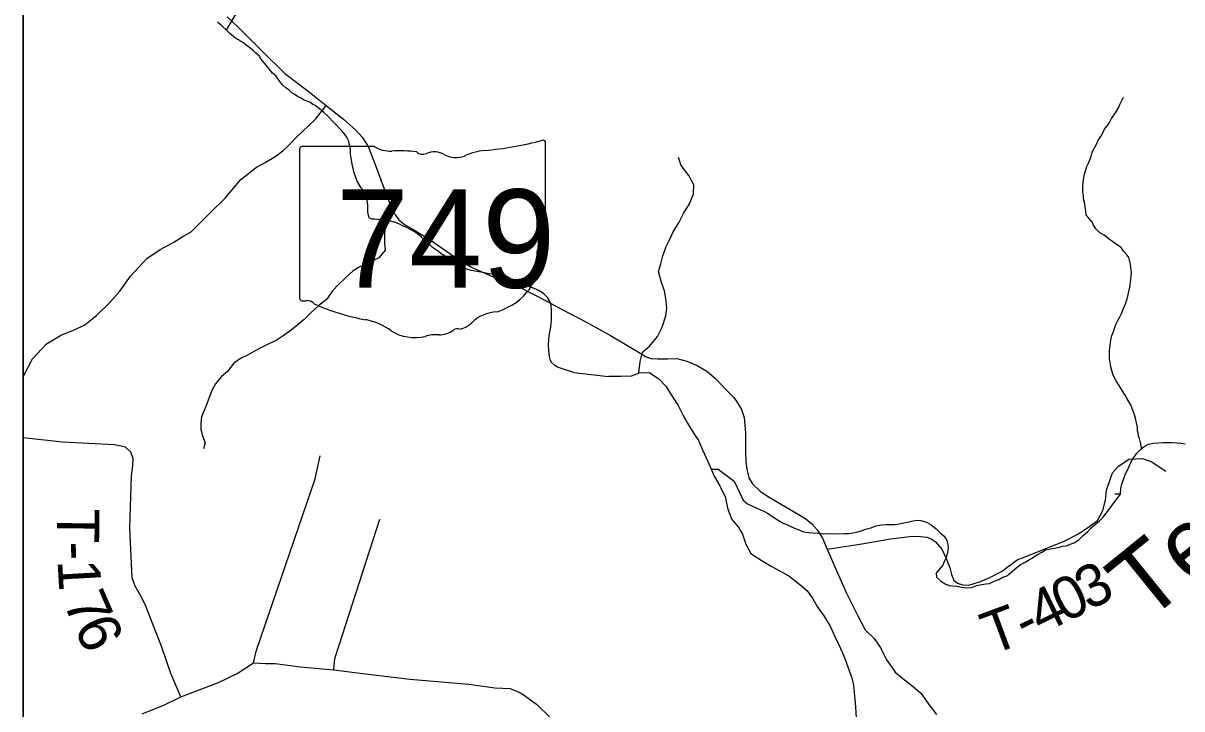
# Model space of a CAD drawing. Extents: x 0 to 39.3, y -3.9 to 22.
# Drawn here: x 1.9 to 3.453, y 16.173 to 17.092 of the extents above; entities that cross this region are included whole.
import ezdxf

# ---------------------------------------------------------------- set-up
doc = ezdxf.new("R2010")
doc.units = 0
for name, color, linetype in [('GM_X_Corporation', 7, 'Continuous'), ('GM_X_Minor_River', 7, 'Continuous'), ('GM_X_Minor_River_Text', 7, 'Continuous'), ('GM_X_State_Location', 7, 'Continuous'), ('GM_X_State_Route', 7, 'Continuous'), ('GM_X_State_Shield', 7, 'Continuous'), ('GM_X_Township_Road', 7, 'Continuous'), ('GM_X_Township_Road_Text', 7, 'Continuous'), ('SH_Data', 7, 'Continuous')]:
    doc.layers.add(name, color=color, linetype=linetype)

msp = doc.modelspace()

# ---------------------------------------------------------------- linework, layer by layer
at = {"layer": 'GM_X_Corporation'}
msp.add_lwpolyline([(1.9, 20.2403), (1.9, 15.8496), (1.9627, 15.8365), (2.054, 15.8197), (2.1447, 15.8042), (2.2384, 15.7885), (2.3314, 15.7727), (2.3534, 15.7684), (2.406, 15.7581), (2.4514, 15.75), (2.5183, 15.7585), (2.5893, 15.7591), (2.6537, 15.7535), (2.8288, 15.7458), (2.8431, 15.7483), (3.5402, 15.8703)], dxfattribs=at)
at = {"layer": 'GM_X_Minor_River'}
for points in [[(2.1724, 17.0821), (2.1899, 17.1123)], [(2.2519, 17.0051), (2.2478, 17.0086), (2.2441, 17.0136), (2.2385, 17.0213), (2.234, 17.0248), (2.2292, 17.031), (2.2251, 17.036), (2.221, 17.0406), (2.218, 17.0445), (2.2169, 17.0476), (2.2116, 17.0515), (2.2087, 17.0545), (2.2034, 17.0592), (2.1985, 17.0627), (2.1952, 17.0654), (2.1914, 17.0674), (2.1884, 17.0694), (2.185, 17.0713), (2.182, 17.0737), (2.1767, 17.0783), (2.1719, 17.0826), (2.1666, 17.0876), (2.1606, 17.093)], [(2.6379, 16.6236), (2.6341, 16.6248), (2.6265, 16.6269), (2.6227, 16.6281), (2.6159, 16.6305), (2.6125, 16.6328), (2.6084, 16.6363), (2.6069, 16.6394), (2.6055, 16.6447), (2.6045, 16.6531), (2.6039, 16.6611), (2.6044, 16.6683), (2.6053, 16.6752), (2.6065, 16.6816), (2.6074, 16.6881), (2.6079, 16.6945), (2.6081, 16.7071), (2.6074, 16.7132), (2.606, 16.7185), (2.6027, 16.7239), (2.5978, 16.7289), (2.5918, 16.7329), (2.5846, 16.736), (2.5778, 16.7388), (2.5631, 16.744), (2.5555, 16.7476), (2.548, 16.7523), (2.5366, 16.7544), (2.5302, 16.7552), (2.5245, 16.7557), (2.52, 16.7566), (2.5135, 16.7578), (2.5002, 16.7603), (2.4946, 16.7619), (2.4904, 16.7635), (2.4833, 16.7671), (2.4795, 16.7694), (2.475, 16.7741), (2.4686, 16.7769), (2.4645, 16.78), (2.4603, 16.7827), (2.4566, 16.7854), (2.4524, 16.7882), (2.4487, 16.7909), (2.4453, 16.794), (2.4416, 16.7971), (2.4378, 16.801), (2.4337, 16.8049), (2.4303, 16.808), (2.427, 16.8103), (2.4239, 16.8123), (2.4206, 16.8142), (2.4164, 16.8166), (2.4123, 16.8185), (2.4085, 16.8201), (2.4051, 16.8217), (2.4002, 16.8241), (2.3953, 16.8253), (2.3919, 16.8261), (2.3873, 16.8266), (2.3843, 16.827), (2.3805, 16.8279), (2.3756, 16.8283), (2.371, 16.8288), (2.3676, 16.8288), (2.3638, 16.8308), (2.3617, 16.8385), (2.3618, 16.8487), (2.3601, 16.8583), (2.3594, 16.8617), (2.3576, 16.8659), (2.3546, 16.8686), (2.352, 16.8721), (2.3475, 16.8798), (2.3457, 16.8848), (2.3435, 16.8909), (2.3421, 16.897), (2.3407, 16.9027), (2.34, 16.9085), (2.3393, 16.913), (2.3386, 16.9172), (2.3387, 16.9214), (2.3384, 16.9245), (2.337, 16.9313), (2.3359, 16.9344), (2.3341, 16.9378), (2.3315, 16.9421), (2.3274, 16.9471), (2.3072, 16.968), (2.3027, 16.9723), (2.299, 16.9757), (2.2914, 16.9812), (2.288, 16.9828), (2.2843, 16.9859), (2.2767, 16.9887), (2.2718, 16.9914), (2.2677, 16.9934), (2.2632, 16.9965), (2.2602, 16.9985), (2.2568, 17.0016), (2.2519, 17.0051)], [(3.3993, 16.5219), (3.3981, 16.524), (3.3974, 16.5297), (3.396, 16.535), (3.3949, 16.5381), (3.3942, 16.5419), (3.3935, 16.545), (3.3932, 16.5499), (3.3921, 16.5557), (3.3907, 16.5621), (3.3889, 16.5679), (3.3867, 16.574), (3.3842, 16.5801), (3.3816, 16.5844), (3.3786, 16.5894), (3.3772, 16.5924), (3.3749, 16.5955), (3.3716, 16.6013), (3.3679, 16.6071), (3.3646, 16.6124), (3.362, 16.6171), (3.3602, 16.6213), (3.3591, 16.6259), (3.3577, 16.6308), (3.3566, 16.6362), (3.3559, 16.6415), (3.3557, 16.6484), (3.3557, 16.6529), (3.3566, 16.6598), (3.3571, 16.6639), (3.3579, 16.6689), (3.3591, 16.673), (3.3607, 16.6772), (3.3619, 16.681), (3.3643, 16.6878), (3.3667, 16.6923), (3.3694, 16.6972), (3.371, 16.7006), (3.3722, 16.7036), (3.3742, 16.7081), (3.3773, 16.7153), (3.3797, 16.7221), (3.3814, 16.7297), (3.383, 16.7377), (3.3843, 16.7475), (3.3853, 16.7574), (3.3849, 16.7608), (3.3839, 16.7688), (3.3825, 16.7738), (3.3818, 16.7776), (3.3796, 16.7807), (3.3751, 16.7857), (3.3714, 16.7911), (3.365, 16.795), (3.3597, 16.7989), (3.356, 16.8017), (3.3485, 16.8075), (3.3428, 16.8106), (3.3376, 16.8161), (3.3342, 16.8207), (3.3332, 16.8245), (3.3283, 16.8303), (3.3246, 16.8342), (3.3243, 16.8399), (3.3233, 16.8452), (3.3229, 16.8494), (3.3212, 16.8563), (3.3208, 16.8601), (3.3202, 16.8654), (3.3203, 16.8727), (3.3207, 16.8772), (3.3212, 16.8822), (3.3225, 16.8894), (3.3241, 16.895), (3.3253, 16.8996), (3.3281, 16.9049), (3.3312, 16.9132), (3.3321, 16.917), (3.3336, 16.9204), (3.3364, 16.9253), (3.3384, 16.9294), (3.3407, 16.9347), (3.345, 16.9411), (3.3493, 16.9494), (3.3544, 16.9561), (3.3564, 16.9595), (3.3583, 16.9641), (3.3607, 16.9671), (3.3649, 16.9727), (3.3677, 16.978), (3.3697, 16.9825), (3.3709, 16.9855), (3.3728, 16.9889), (3.3748, 16.9927)], [(2.725, 16.6228), (2.7269, 16.6383), (2.7298, 16.6505), (2.7394, 16.6587), (2.7499, 16.6718), (2.7562, 16.6842), (2.7614, 16.6993), (2.7627, 16.7103), (2.7614, 16.7225), (2.7593, 16.7328), (2.7553, 16.7439), (2.7514, 16.7588), (2.7546, 16.769), (2.7571, 16.7796), (2.7619, 16.7921), (2.7666, 16.8023), (2.7713, 16.8121), (2.7791, 16.8249), (2.785, 16.8366), (2.7929, 16.8493), (2.7984, 16.8629), (2.7986, 16.8751), (2.792, 16.8874), (2.7816, 16.9009), (2.7783, 16.9116)], [(2.3848, 16.827), (2.3841, 16.7966), (2.3851, 16.7875), (2.3766, 16.7769), (2.3609, 16.7696), (2.3505, 16.7645), (2.3421, 16.7597), (2.332, 16.7503), (2.3228, 16.7414), (2.3146, 16.7328), (2.3068, 16.7219), (2.2964, 16.7133), (2.2856, 16.7032), (2.2767, 16.6946), (2.2659, 16.6857), (2.2575, 16.679), (2.2486, 16.6727), (2.239, 16.6664), (2.2294, 16.662), (2.2187, 16.6565), (2.2102, 16.652), (2.2006, 16.6465), (2.1914, 16.6421), (2.1822, 16.6358), (2.1737, 16.6249), (2.1652, 16.6174), (2.1578, 16.6084), (2.1531, 16.6002), (2.1491, 16.59), (2.1463, 16.5813), (2.1424, 16.5726), (2.1388, 16.5639), (2.1379, 16.5555), (2.1381, 16.5468), (2.1403, 16.5384), (2.1439, 16.5292), (2.1415, 16.5209)], [(2.6379, 16.6236), (2.6844, 16.6182), (2.6852, 16.6186)], [(2.6852, 16.6186), (2.7009, 16.6185), (2.7152, 16.6188), (2.7259, 16.6231), (2.7388, 16.6233), (2.752, 16.6151), (2.7613, 16.6051), (2.7713, 16.5893), (2.778, 16.5793), (2.7846, 16.5659), (2.7905, 16.5555), (2.7986, 16.5417), (2.8049, 16.5321), (2.8108, 16.5187), (2.8152, 16.5091), (2.8196, 16.4991), (2.8262, 16.4846), (2.8336, 16.4715)], [(3.3706, 16.4604), (3.3708, 16.4679), (3.3724, 16.4736), (3.3744, 16.48), (3.3767, 16.4868), (3.3795, 16.4917), (3.3818, 16.4966), (3.3846, 16.5027), (3.3877, 16.5079), (3.3923, 16.5151), (3.3974, 16.5203), (3.4024, 16.5244), (3.4081, 16.5274), (3.415, 16.5288), (3.421, 16.5291), (3.4275, 16.5294), (3.4336, 16.5297), (3.4397, 16.5296), (3.4465, 16.5291), (3.4514, 16.5286), (3.4571, 16.5278)], [(2.8219, 16.4939), (2.8313, 16.494), (2.8529, 16.4778)], [(2.8529, 16.4778), (2.8649, 16.4524), (2.8705, 16.4474), (2.8773, 16.4442), (2.8871, 16.4399), (2.8927, 16.4375), (2.8976, 16.4348), (2.9025, 16.4316), (2.9081, 16.4278), (2.913, 16.4246), (2.9183, 16.4215), (2.9232, 16.4195), (2.9288, 16.4171), (2.9337, 16.4148), (2.9386, 16.4128), (2.9457, 16.41), (2.9525, 16.4088), (2.9578, 16.4083), (2.9662, 16.4078), (2.973, 16.4073), (2.9783, 16.4076), (2.9942, 16.4073), (3.0007, 16.4076), (3.0064, 16.4075), (3.0124, 16.4085), (3.0185, 16.4099), (3.0235, 16.4113), (3.0288, 16.4132), (3.0361, 16.4153), (3.0433, 16.4179), (3.0505, 16.4193), (3.0562, 16.4195), (3.0627, 16.4198), (3.0676, 16.4197), (3.0744, 16.4207), (3.0801, 16.4218), (3.0851, 16.4228), (3.0927, 16.4246), (3.0976, 16.4253), (3.1029, 16.4252), (3.1105, 16.4228), (3.1169, 16.4193), (3.1229, 16.4142), (3.1288, 16.4084), (3.1344, 16.4041), (3.1377, 16.398), (3.1392, 16.393), (3.1395, 16.3873), (3.1382, 16.3801), (3.137, 16.3752), (3.1342, 16.3699), (3.1323, 16.365), (3.1272, 16.359), (3.1234, 16.3542), (3.124, 16.3492), (3.1296, 16.3438), (3.1356, 16.3399), (3.1409, 16.3379), (3.1462, 16.3374), (3.1511, 16.337), (3.1575, 16.3357), (3.164, 16.3349), (3.1712, 16.3351), (3.1781, 16.3377), (3.1849, 16.3394), (3.1902, 16.3401), (3.1952, 16.3404), (3.2013, 16.3437), (3.2074, 16.3459), (3.2131, 16.3492), (3.2181, 16.351), (3.2231, 16.3548), (3.2296, 16.3603), (3.2365, 16.3659), (3.2426, 16.3692), (3.2518, 16.3744), (3.2595, 16.3792), (3.2652, 16.3825), (3.2702, 16.3855), (3.2794, 16.3876), (3.287, 16.389), (3.2927, 16.3904), (3.298, 16.3911), (3.303, 16.3933), (3.3083, 16.3951), (3.3152, 16.3996), (3.3206, 16.4048), (3.3263, 16.4096), (3.3314, 16.4152), (3.3375, 16.4205), (3.3425, 16.4246), (3.3475, 16.4294), (3.3706, 16.4604), (3.3628, 16.4603)], [(2.8336, 16.4715), (2.8351, 16.4686), (2.8406, 16.4567), (2.8445, 16.4403), (2.8496, 16.4265), (2.8581, 16.4165), (2.864, 16.4065), (2.8683, 16.3931), (2.875, 16.3808), (2.8889, 16.3719), (2.9024, 16.3636), (2.9155, 16.3566), (2.9261, 16.3507), (2.9407, 16.3394), (2.9508, 16.3309), (2.9578, 16.3208), (2.9641, 16.3097), (2.973, 16.2974), (2.9815, 16.2835), (2.9877, 16.2697), (2.9928, 16.259), (2.9979, 16.2475), (3.0023, 16.2364), (3.0059, 16.2261), (3.0103, 16.2142), (3.0128, 16.2043), (3.0153, 16.1754), (3.0162, 16.1601)]]:
    msp.add_lwpolyline(points, dxfattribs=at)
at = {"layer": 'GM_X_State_Route'}
msp.add_lwpolyline([(2.1736, 17.1004), (2.1889, 17.0854), (2.22, 17.0544), (2.2505, 17.0244), (2.2814, 17.0011), (2.3061, 16.9812), (2.3293, 16.9629), (2.3456, 16.9481), (2.3541, 16.9389), (2.3624, 16.9264), (2.3718, 16.9023), (2.3836, 16.8696), (2.3926, 16.8464), (2.3987, 16.8346), (2.4035, 16.8281), (2.411, 16.8219), (2.4213, 16.8161), (2.4439, 16.8022), (2.4673, 16.7861), (2.4836, 16.7751), (2.501, 16.7644), (2.5234, 16.7544), (2.5642, 16.7384), (2.6016, 16.7191), (2.6207, 16.7088), (2.6542, 16.6912), (2.6873, 16.6732), (2.7189, 16.6542), (2.7347, 16.6442), (2.7411, 16.6422), (2.7502, 16.6416), (2.7639, 16.6417), (2.7761, 16.6421), (2.7892, 16.6387), (2.8032, 16.6327), (2.816, 16.6251), (2.8278, 16.6154), (2.8426, 16.5998), (2.8522, 16.5897), (2.8575, 16.5827), (2.8625, 16.574), (2.8661, 16.5629), (2.8678, 16.5423), (2.8682, 16.5184), (2.8683, 16.5035), (2.8698, 16.4939), (2.8726, 16.4821), (2.8773, 16.4743), (2.8876, 16.4643), (2.8975, 16.4577), (2.9171, 16.446), (2.9384, 16.4335), (2.9488, 16.4271), (2.9571, 16.4206), (2.964, 16.4123), (2.9712, 16.4012), (2.9776, 16.3867), (2.9891, 16.3596), (3.0033, 16.3277), (3.0185, 16.2971), (3.0283, 16.2785), (3.0403, 16.2666), (3.0483, 16.2554), (3.0574, 16.2378), (3.0686, 16.2216), (3.0787, 16.2132), (3.0932, 16.2022), (3.103, 16.1937), (3.1152, 16.1765), (3.1238, 16.1647)], dxfattribs=at)
at = {"layer": 'GM_X_State_Shield'}
for p, q in [((2.3703, 16.9264), (2.2738, 16.9264)), ((2.6001, 16.8267), (2.6001, 16.9314)), ((2.2705, 16.923), (2.2705, 16.7229)), ((2.6001, 16.8267), (2.6001, 16.8267))]:
    msp.add_line(p, q, dxfattribs=at)
for centre, major_axis, start_param, end_param in [((2.2743, 16.9234), (0.00382, 0), 1.712693, 3.28349), ((2.3933, 16.9497), (0.037, 0), 4.042523, 4.731795), ((2.4827, 17.1993), (0.3495, 0), 4.814394, 5.042369), ((2.5964, 16.9318), (0.00367, 0), 6.141152, 7.989035), ((2.4055, 16.8141), (0.133, 0), 1.404758, 1.657858), ((2.4357, 16.9244), (0.0107, 0), 3.836095, 5.185415), ((2.4514, 16.9013), (0.0222, 0), 0.950623, 2.079405), ((2.4801, 16.933), (0.0267, 0), 4.081561, 5.145723), ((2.5273, 16.8653), (0.0703, 0), 1.699011, 2.107814), ((2.5992, 16.819), (0.00568, 0), 1.883978, 3.671073), ((2.5631, 16.8058), (0.0341, 0), 5.934695, 6.695948), ((2.5962, 16.8263), (0.00393, 0), 5.05454, 6.418171), ((2.6132, 16.7829), (0.0248, 0), 2.387724, 3.262537), ((2.5023, 16.7696), (0.0874, 0), 5.101752, 6.440018), ((2.2743, 16.7224), (0.00385, 0), 3.00124, 4.508301), ((2.2749, 16.7429), (0.0294, 0), 4.665946, 4.897461), ((2.2809, 16.7113), (0.0106, 0), 0.519207, 1.627899), ((2.4147, 16.8911), (0.2524, 0), 4.195997, 4.488961), ((2.3395, 16.633), (0.079, 0), 0.823519, 1.323587), ((2.5391, 16.6667), (0.0479, 0), 1.647645, 2.488434), ((2.4249, 16.7103), (0.0501, 0), 4.026481, 4.996735), ((2.4575, 16.6953), (0.0267, 0), 4.691044, 5.507374), ((2.4817, 16.676), (0.00752, 0), 1.147584, 2.315152), ((2.4785, 16.7035), (0.0282, 0), 4.937069, 5.64225), ((2.4539, 16.6411), (0.0412, 0), 1.495662, 1.94098)]:
    msp.add_ellipse(centre, major_axis=major_axis, ratio=0.8, start_param=start_param, end_param=end_param, dxfattribs=at)
at = {"layer": 'GM_X_Township_Road'}
for points in [[(1.9, 16.6176), (1.9123, 16.6418), (1.9313, 16.6619), (1.9512, 16.6741), (1.9689, 16.6804), (1.9827, 16.6874), (1.9982, 16.6998), (2.0152, 16.7163), (2.0295, 16.7325), (2.0439, 16.7527), (2.0659, 16.7762), (2.0836, 16.7885), (2.1019, 16.798), (2.1141, 16.8058), (2.1256, 16.8126), (2.15, 16.8372), (2.1705, 16.8573), (2.1919, 16.8823), (2.2127, 16.8987), (2.2242, 16.9049), (2.2384, 16.9133), (2.2481, 16.9207), (2.255, 16.9271), (2.2655, 16.9382), (2.2917, 16.9632), (2.3061, 16.9812)], [(2.1114, 16.1885), (2.098, 16.2199), (2.0858, 16.2554), (2.0635, 16.3124), (2.0567, 16.3254), (2.0499, 16.3371), (2.0459, 16.3481), (2.0428, 16.4152), (2.045, 16.4849), (2.0471, 16.4989), (2.0475, 16.5079), (2.0444, 16.5166), (2.037, 16.5233), (2.0224, 16.5264), (1.9528, 16.5302), (1.9, 16.536)], [(2.2088, 16.2342), (2.2129, 16.251), (2.2574, 16.3815), (2.2915, 16.4808), (2.2978, 16.5118)], [(3.2239, 16.3661), (3.2274, 16.3685), (3.2332, 16.3729), (3.2405, 16.3753), (3.2953, 16.3971), (3.3142, 16.4072), (3.3296, 16.4174), (3.3397, 16.4248), (3.3468, 16.4383), (3.3506, 16.4522), (3.3518, 16.4655), (3.3597, 16.4887), (3.3674, 16.4974), (3.3819, 16.507), (3.3997, 16.508), (3.4118, 16.504), (3.4313, 16.4913)], [(2.3164, 16.2248), (2.3177, 16.2399), (2.3233, 16.2578), (2.3779, 16.427)], [(2.9776, 16.3867), (3.0241, 16.3936), (3.0622, 16.4005), (3.0881, 16.4037), (3.0979, 16.4038), (3.1112, 16.4027), (3.1168, 16.4002), (3.1224, 16.3967), (3.1312, 16.3866), (3.1373, 16.3731), (3.1419, 16.3616), (3.1443, 16.3524), (3.1472, 16.3451), (3.152, 16.3408), (3.1591, 16.3387), (3.1674, 16.3381), (3.1831, 16.343), (3.1954, 16.3484), (3.2119, 16.3571), (3.2205, 16.3637), (3.2239, 16.3661)], [(2.0593, 16.1657), (2.0893, 16.178), (2.1114, 16.1885), (2.1618, 16.2079), (2.1869, 16.22), (2.2088, 16.2342), (2.2247, 16.2335), (2.2378, 16.2335), (2.2715, 16.2288), (2.3164, 16.2248), (2.3554, 16.2199), (2.4183, 16.2123), (2.4972, 16.2054), (2.5323, 16.2008), (2.5526, 16.1997), (2.5673, 16.1934), (2.5879, 16.1789), (2.6052, 16.1618)]]:
    msp.add_lwpolyline(points, dxfattribs=at)
at = {"layer": 'SH_Data'}
msp.add_lwpolyline([(1.9, 21.1), (9.1, 21.1), (9.1, 13.9), (1.9, 13.9)], close=True, dxfattribs=at)

# ---------------------------------------------------------------- texts
at = {"layer": 'GM_X_Minor_River_Text'}
msp.add_text('Tenmile', height=0.09471, rotation=39.0098, dxfattribs=at).set_placement((3.4042, 16.2867))
at = {"layer": 'GM_X_State_Location'}
for s in ['s', 'r']:
    msp.add_text(s, height=0.000189, dxfattribs=at).set_placement((2.4316, 16.8096))
msp.add_text('749', height=0.000189, rotation=0, dxfattribs=at).set_placement((2.3647, 16.7958))
at = {"layer": 'GM_X_State_Shield'}
msp.add_text('749', height=0.13184, dxfattribs=at).set_placement((2.319, 16.737))
at = {"layer": 'GM_X_Township_Road_Text'}
for s, rotation, p in [('T', 269.6357, (1.9453, 16.4412)), ('-', 272.1041, (1.9451, 16.3961)), ('1', 273.2718, (1.946, 16.3715)), ('3', 27.6027, (3.3284, 16.3036)), ('0', 26.2489, (3.2957, 16.2874)), ('4', 26.1741, (3.2642, 16.2719)), ('7', 293.5355, (1.9531, 16.3154)), ('T', 20.3895, (3.1976, 16.2443)), ('6', 294.4423, (1.9675, 16.2824)), ('-', 26.3166, (3.2434, 16.2616))]:
    msp.add_text(s, height=0.0568, rotation=rotation, dxfattribs=at).set_placement(p)

doc.saveas('drawing.dxf')
